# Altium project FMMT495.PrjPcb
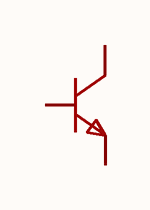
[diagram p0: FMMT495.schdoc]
1 sheet, 1 parts. Net scope: global (net labels, ports and power ports of the same name join across sheets).

## Sheet FMMT495.schdoc
size 127 x 101 mm

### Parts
Q?  fmmt495  [SOT-23-3_L2.9-W1.3-P1.90-LS2.4-BR]  (value not drawn)

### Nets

Not connected (* = marked no-connect by the designer): Q? 1(B) 2(E) 3(C)

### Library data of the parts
Q? = fmmt495: 晶体管类型:NPN;集电极电流(Ic):1A;集射极击穿电压(Vceo):150V;耗散功率(Pd):250mW;直流电流增益(hFE):100;; Manufacturer: CJ(江苏长电/长晶); AddInBom: yes; ModelId: c62791f0466c4ae2a892c056b845b0ca; ModelName: SOT-23-3P_L2.9-W1.3-H1.0-LS2.4-P0.95; ModelTransform: 98.425,114.173,0,180,0,0,0.0005,-0.0005,0; type: NPN; Current - Collector(Ic): 1A; Collector - Emitter Voltage VCEO: 150V; Pd - Power Dissipation: 250mW; DC Current Gain: 100; Transition frequency(fT): 100MHz; Current - Collector Cutoff: 100nA; Vce Saturation(VCE(sat)): 300mV; Emitter-Base Voltage(Vebo): 5V; Number: 1个NPN; Configuration: 独立式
